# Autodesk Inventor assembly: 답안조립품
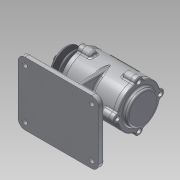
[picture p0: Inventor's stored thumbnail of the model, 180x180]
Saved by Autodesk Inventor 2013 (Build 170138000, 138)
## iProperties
Created: 2015-12
Part Number: 답안조립품
Document SubType Name: Assembly
Designer: Administrator
Author: Administrator
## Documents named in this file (8)
- C:\Users\Administrator\Desktop\451208V1018\답안조립품.iam
- C:\Users\Administrator\Desktop\451208V1018\본체.ipt
- C:\Users\Administrator\Desktop\451208V1018\커버.ipt
- C:\Users\Administrator\Desktop\451208V1018\커버2.ipt
- C:\Users\Administrator\Desktop\451208V1018\베어링 6204.ipt
- C:\Users\Administrator\Desktop\451208V1018\축.ipt
- C:\Users\Administrator\Desktop\451208V1018\키(4 x 4 x 12).ipt
- C:\Users\Administrator\Desktop\451208V1018\V-벨트풀리.ipt
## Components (4 placed, 3 different names)
1. KS B 2023 6204 - 20 x 47 x 14:1
2. KS B 2023 6204 - 20 x 47 x 14:2
3. KS B 1311 (I) 4 x 4 x 12:1
4. V-벨트풀리:1
